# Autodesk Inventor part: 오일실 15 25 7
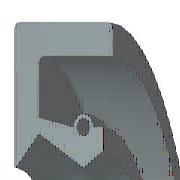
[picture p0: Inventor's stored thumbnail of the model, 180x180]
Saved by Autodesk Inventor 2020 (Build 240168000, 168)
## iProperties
Created: 2012-02
Part Number: 오일실 15 25 7
Material: 고무
Description: 오일-실
Document SubType Name: Modeling
Standard: KS B 2804
Designer: mduedu
Standards Organization: KS
Language: ko-KR
Size Designation: D - 15 25 7
Categories: <MemberInstance><Categories><Category DisplayName="샤프트 부품" InternalName="7f7aeb1f-a693-4053-b835-cee3144e0d98" Mnemonic="SHFT"><Category DisplayName="실링" Intern
Density: 0.93 g/cm^3
Appearance: 고무 - 검은색 - 버전 1.1
IsCustomPart: 1
Author: mduedu
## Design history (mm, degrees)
revolve "본체" stored, may be unused: angle "d17" = 90 deg
revolve "스프링1" stored, may be unused: angle "d18" = 90 deg
body "Solid1"
sketch "스케치1"
  geometry: L1 (0, 12.5)-(7, 12.5); L2 (7, 10.75)-(1.75, 10.75); L3 (1.75, 9.25)-(4.9, 7.5); L4 (4.9, 7.5)-(0, 7.5); L5 (0, 0)-(9.586, 0) reference; L6 (4.9, 7.5)-(6.3, 8.375); L7 (0, 18)-(0, -3) reference; L8 (-1.941, 0)-(11.507, 0) reference; L9 (4.2, 9.6)-(1.75, 10.09); L10 (1.75, 10.09)-(1.75, 10.75); L11 (0, 12.5)-(0, 7.588); L12 (4.9, 7.5)-(0, 7.5); L13 (1.75, 9.25)-(0.152, 7.528); L14 (7, 12.5)-(7, 10.75); L15 (5.6, 9.6)-(6.3, 9.6); L16 (6.3, 9.6)-(6.3, 8.375); C1 r 0.455 at (4.9, 9.6); A1 r 0.7 centre (4.9, 9.6) between (5.6, 9.6) and (4.2, 9.6); A2 r 0.088 centre (0.088, 7.588) between (0, 7.588) and (0.152, 7.528); 1 further point
  constraints: 28 end point, 5 horizontal alignment, 5 point on line, 4 point on circle, 4 vertical alignment, 3 centre point, 3 tangent, 2 collinear, 2 horizontal, 2 perpendicular, 1 coincident, 1 parallel
  dimensions: "d0" = 25 diameter of L1 L5 (= SD2); "d1" = 1.75 distance of L1.end L2.start (= SD); "d2" = 0.91 diameter of C1 (= SPDI); "d3" = 1.4 diameter of A1 (= SPDA); "d4" = 15 diameter of L3.end L5 (= NND); "d5" = 18.5 diameter of L3.start L5 (= TKDM); "d7" = 20.18 diameter of L9.end L5 (= TKDM + 0.24 x SWDT); "d8" = 1.75 distance between parallel lines of L11 L10 (= SD); "d9" = 4.9 distance from line of L11 C1.centre (= SPDST); "d10" = 19.2 diameter of C1.centre L5 (= HLDM); "d11" = 0.0875 radius of A2 (= 0.25 x LAB); "d12" = 6.3 distance between parallel lines of L11 L16 (= SDI); "d13" = 16.75 diameter of L6.end L5 (= ABDM); "d14" = 7 distance from line of L11 L1.end (= SWDT)
fillet "모깎기1" dims "d6" = 0.3 (= RR)
other parameters: "SD2" = 25 [user parameter; used in 1 equation term], "SWDT" = 7 [user parameter; used in 2 equation terms], "RR" = 0.3 [user parameter; used in 1 equation term], "SD" = 1.75 [user parameter; used in 2 equation terms], "NND" = 15 [user parameter; used in 1 equation term], "SPDA" = 1.4 [user parameter; used in 1 equation term], "SPDI" = 0.91 [user parameter; used in 1 equation term], "TKDM" = 18.5 [user parameter; used in 2 equation terms], "HLDM" = 19.2 [user parameter; used in 1 equation term], "ABDM" = 16.75 [user parameter; used in 1 equation term], "SDI" = 6.3 [user parameter; used in 1 equation term], "SPDST" = 4.9 [user parameter; used in 1 equation term], "LAB" = 0.35 [user parameter; used in 1 equation term], "d15" = 0, "d16" = 0, "d19" = 0
